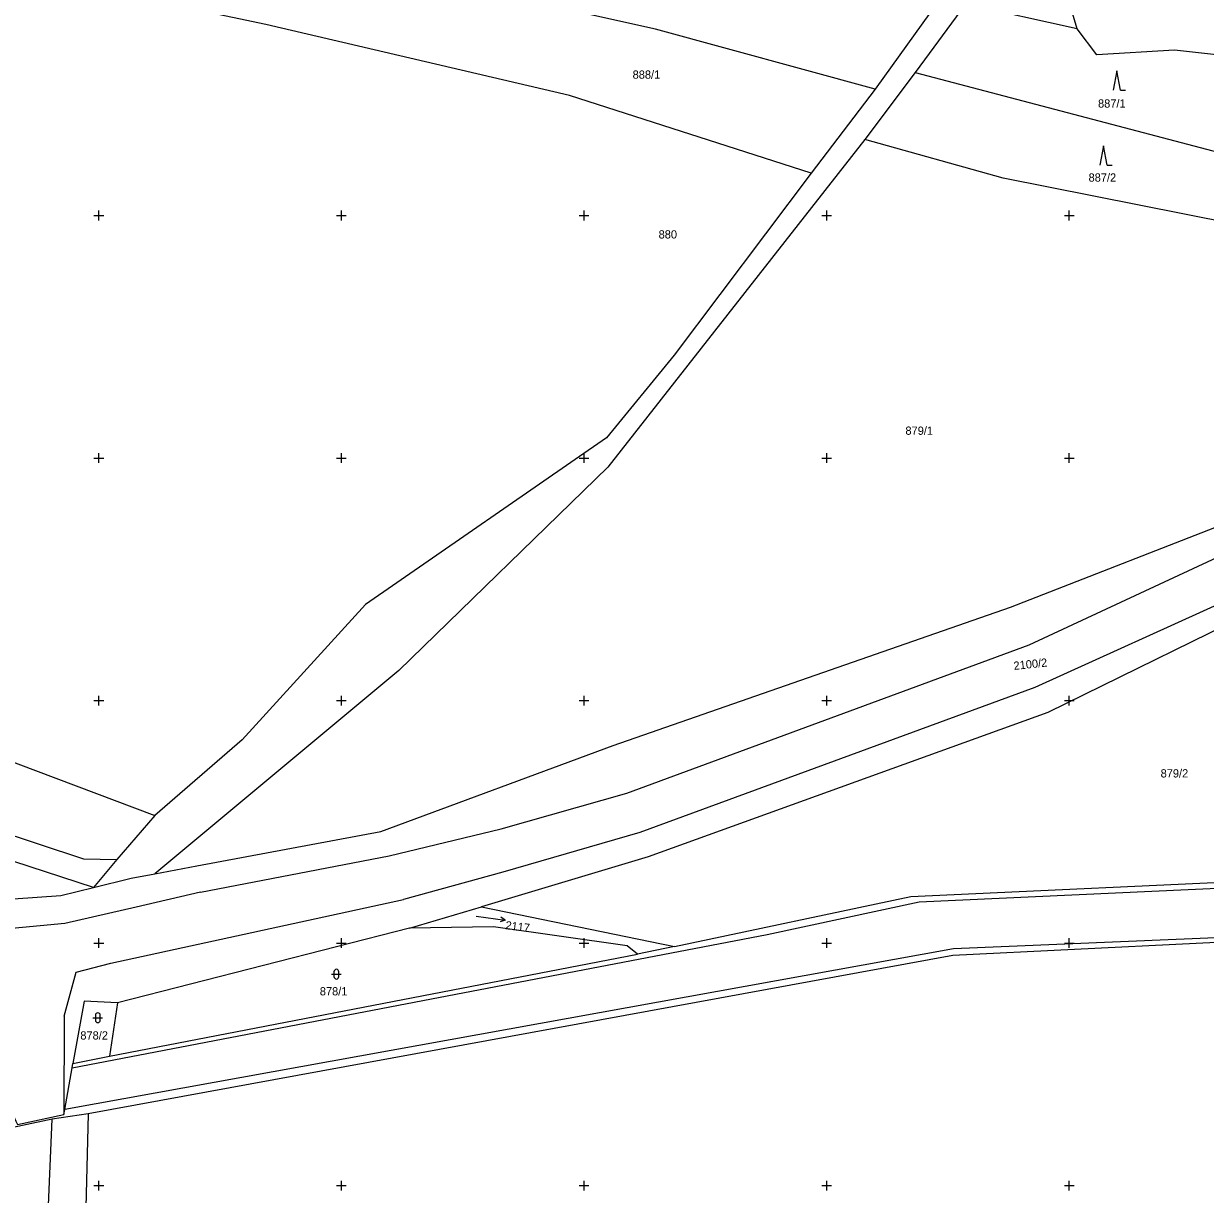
# Model space of a CAD drawing. Extents: x -776734 to -748832, y -1118122 to -976986.
# Drawn here: x -751615.5 to -751372, y -1114601.8 to -1114360.4 of the extents above; entities that cross this region are included whole.
import ezdxf

# ---------------------------------------------------------------- set-up
doc = ezdxf.new("R2010")
doc.units = 0
for name, color, linetype in [('KM_Hranice parcel', 7, 'Continuous'), ('KM_Parcelní čísla', 7, 'Continuous'), ('KM_Vnitřní kresba', 7, 'Continuous'), ('KM_Značky kultur', 7, 'Continuous'), ('Level 61 Křížky', 7, 'Continuous')]:
    doc.layers.add(name, color=color, linetype=linetype)

msp = doc.modelspace()

# ---------------------------------------------------------------- linework, layer by layer
at = {"layer": 'KM_Hranice parcel'}
for p, q in [((-751427.05, -1114355.89), (-751440, -1114373.97)), ((-751421.39, -1114356.4), (-751431.74, -1114370.53)), ((-751398.35, -1114361.51), (-751421.39, -1114356.4)), ((-751431.74, -1114370.53), (-751442.11, -1114384.32)), ((-751431.74, -1114370.53), (-751341.58, -1114394.27)), ((-751440, -1114373.97), (-751453.2, -1114391.28)), ((-751601.09, -1114538.53), (-751689.64, -1114509.75)), ((-751621.83, -1114511.12), (-751588.44, -1114523.72)), ((-751588.44, -1114523.72), (-751596.28, -1114532.8)), ((-751596.28, -1114532.8), (-751601.09, -1114538.53)), ((-751535.95, -1114546.94), (-751521.15, -1114542.51)), ((-751521.15, -1114542.51), (-751481.36, -1114550.68)), ((-751535.95, -1114546.94), (-751596.18, -1114562.31)), ((-751518.68, -1114546.66), (-751535.95, -1114546.94)), ((-751597.79, -1114573.33), (-751488.98, -1114552.3)), ((-751481.36, -1114550.68), (-751488.98, -1114552.3)), ((-751603.05, -1114561.97), (-751605.33, -1114574.82)), ((-751596.18, -1114562.31), (-751603.05, -1114561.97)), ((-751596.18, -1114562.31), (-751597.79, -1114573.33)), ((-751605.33, -1114574.82), (-751597.79, -1114573.33)), ((-751609.62, -1114586.32), (-751642.03, -1114593.16)), ((-751610.82, -1114613.8), (-751609.62, -1114586.32)), ((-751602.21, -1114585.19), (-751609.62, -1114586.32)), ((-751602.21, -1114585.19), (-751603.5, -1114635.12))]:
    msp.add_line(p, q, dxfattribs=at)
for points in [[(-751440, -1114373.97), (-751485.27, -1114361.58), (-751742.99, -1114304.3)], [(-751453.2, -1114391.28), (-751503.01, -1114375.24), (-751565.59, -1114360.64), (-751686.33, -1114335.17), (-751745.07, -1114320.79)], [(-751398.35, -1114361.51), (-751403.83, -1114343.32), (-751398.45, -1114331.48)], [(-751341.58, -1114394.27), (-751342.07, -1114392.17), (-751351.85, -1114388.94), (-751349.21, -1114369.18), (-751378.31, -1114365.92), (-751394.34, -1114366.89), (-751398.35, -1114361.51)], [(-751442.11, -1114384.32), (-751495.07, -1114451.91), (-751538.14, -1114493.82), (-751588.46, -1114535.7)], [(-751338.56, -1114407.2), (-751413.61, -1114392.32), (-751442.11, -1114384.32)], [(-751453.2, -1114391.28), (-751481.44, -1114428.78), (-751495.4, -1114445.83), (-751545.06, -1114480.22), (-751570.45, -1114508.09), (-751588.44, -1114523.72)], [(-751588.46, -1114535.7), (-751579.83, -1114534.11), (-751541.9, -1114526.98), (-751493.98, -1114509.24), (-751412.14, -1114480.78), (-751314.14, -1114442.52)], [(-751308.12, -1114455.16), (-751404.41, -1114502.47), (-751486.76, -1114532.2), (-751521.15, -1114542.51)], [(-751481.36, -1114550.68), (-751432.68, -1114540.38), (-751355.26, -1114536.81), (-751275.2, -1114497.24)], [(-751687.49, -1114504.72), (-751603.17, -1114532.66), (-751596.28, -1114532.8)], [(-751268.49, -1114506.51), (-751348.8, -1114548.84), (-751424.02, -1114552.57), (-751602.21, -1114585.19)], [(-751601.09, -1114538.53), (-751593.31, -1114536.6), (-751588.46, -1114535.7)], [(-751665.45, -1114544.23), (-751607.84, -1114540.2), (-751601.09, -1114538.53)], [(-751488.98, -1114552.3), (-751491.11, -1114550.56), (-751518.68, -1114546.66)], [(-751621.11, -1114577.93), (-751620.76, -1114578.69), (-751617.1, -1114586.71), (-751616.79, -1114587.38), (-751607.19, -1114585.33), (-751607, -1114584.28), (-751605.49, -1114575.75), (-751605.33, -1114574.82)]]:
    msp.add_lwpolyline(points, dxfattribs=at)
at = {"layer": 'KM_Vnitřní kresba'}
for p, q in [((-751408.27, -1114488.53), (-751313.34, -1114444.27)), ((-751309.29, -1114452.86), (-751407.07, -1114497.33)), ((-751491.18, -1114519.1), (-751408.27, -1114488.53)), ((-751407.07, -1114497.33), (-751488.49, -1114527.19)), ((-751517.11, -1114526.48), (-751491.18, -1114519.1)), ((-751540.16, -1114532.01), (-751517.11, -1114526.48)), ((-751488.49, -1114527.19), (-751516.72, -1114535.38)), ((-751579.06, -1114539.53), (-751540.16, -1114532.01)), ((-751516.72, -1114535.38), (-751537.2, -1114541.02)), ((-751579.06, -1114539.53), (-751592.28, -1114542.58)), ((-751430.97, -1114541.48), (-751354.45, -1114537.96)), ((-751592.28, -1114542.58), (-751606.98, -1114545.97)), ((-751597.53, -1114554.13), (-751537.2, -1114541.02)), ((-751462.24, -1114548.25), (-751430.97, -1114541.48)), ((-751606.98, -1114545.97), (-751685.68, -1114553.29)), ((-751531.41, -1114561.5), (-751462.24, -1114548.25)), ((-751350.22, -1114548.07), (-751423.89, -1114551.2)), ((-751423.89, -1114551.2), (-751607, -1114584.28)), ((-751604.68, -1114556.02), (-751597.53, -1114554.13)), ((-751607.11, -1114565.08), (-751604.68, -1114556.02)), ((-751605.49, -1114575.75), (-751531.41, -1114561.5)), ((-751607.11, -1114565.08), (-751607.19, -1114585.33))]:
    msp.add_line(p, q, dxfattribs=at)
at = {"layer": 'KM_Značky kultur'}
for p, q in [((-751390.19, -1114370.17), (-751390.94, -1114374.17)), ((-751389.44, -1114374.17), (-751390.19, -1114370.17)), ((-751389.44, -1114374.17), (-751388.444, -1114374.17)), ((-751392.93, -1114385.63), (-751393.68, -1114389.63)), ((-751392.18, -1114389.63), (-751392.93, -1114385.63)), ((-751392.18, -1114389.63), (-751391.184, -1114389.63)), ((-751522.205, -1114544.423), (-751516.263, -1114545.258)), ((-751516.263, -1114545.258), (-751517.161, -1114544.626)), ((-751516.263, -1114545.258), (-751517.301, -1114545.619)), ((-751552.041, -1114556.411), (-751550.039, -1114556.411)), ((-751551.541, -1114555.911), (-751551.541, -1114556.912)), ((-751550.539, -1114556.912), (-751550.539, -1114555.911)), ((-751601.211, -1114565.381), (-751599.209, -1114565.381)), ((-751600.711, -1114564.881), (-751600.711, -1114565.882)), ((-751599.709, -1114565.882), (-751599.709, -1114564.881))]:
    msp.add_line(p, q, dxfattribs=at)
for centre, start, end in [((-751551.04, -1114555.9109), 0, 180), ((-751551.04, -1114556.9109), 180, 359.987886), ((-751600.21, -1114564.8809), 0, 180), ((-751600.21, -1114565.8809), 180, 359.987886)]:
    msp.add_arc(centre, 0.5, start, end, dxfattribs=at)
at = {"layer": 'Level 61 Křížky'}
for p, q in [((-751600, -1114400), (-751600, -1114399)), ((-751550, -1114400), (-751550, -1114399)), ((-751500, -1114400), (-751500, -1114399)), ((-751450, -1114400), (-751450, -1114399)), ((-751400, -1114400), (-751400, -1114399)), ((-751601, -1114400), (-751599, -1114400)), ((-751600, -1114401), (-751600, -1114400)), ((-751551, -1114400), (-751549, -1114400)), ((-751550, -1114401), (-751550, -1114400)), ((-751501, -1114400), (-751499, -1114400)), ((-751500, -1114401), (-751500, -1114400)), ((-751451, -1114400), (-751449, -1114400)), ((-751450, -1114401), (-751450, -1114400)), ((-751401, -1114400), (-751399, -1114400)), ((-751400, -1114401), (-751400, -1114400)), ((-751601, -1114450), (-751599, -1114450)), ((-751600, -1114450), (-751600, -1114449)), ((-751600, -1114451), (-751600, -1114450)), ((-751551, -1114450), (-751549, -1114450)), ((-751550, -1114450), (-751550, -1114449)), ((-751550, -1114451), (-751550, -1114450)), ((-751501, -1114450), (-751499, -1114450)), ((-751500, -1114450), (-751500, -1114449)), ((-751500, -1114451), (-751500, -1114450)), ((-751451, -1114450), (-751449, -1114450)), ((-751450, -1114450), (-751450, -1114449)), ((-751450, -1114451), (-751450, -1114450)), ((-751401, -1114450), (-751399, -1114450)), ((-751400, -1114450), (-751400, -1114449)), ((-751400, -1114451), (-751400, -1114450)), ((-751601, -1114500), (-751599, -1114500)), ((-751600, -1114500), (-751600, -1114499)), ((-751600, -1114501), (-751600, -1114500)), ((-751551, -1114500), (-751549, -1114500)), ((-751550, -1114500), (-751550, -1114499)), ((-751550, -1114501), (-751550, -1114500)), ((-751501, -1114500), (-751499, -1114500)), ((-751500, -1114500), (-751500, -1114499)), ((-751500, -1114501), (-751500, -1114500)), ((-751451, -1114500), (-751449, -1114500)), ((-751450, -1114500), (-751450, -1114499)), ((-751450, -1114501), (-751450, -1114500)), ((-751401, -1114500), (-751399, -1114500)), ((-751400, -1114500), (-751400, -1114499)), ((-751400, -1114501), (-751400, -1114500)), ((-751601, -1114550), (-751599, -1114550)), ((-751600, -1114550), (-751600, -1114549)), ((-751600, -1114551), (-751600, -1114550)), ((-751551, -1114550), (-751549, -1114550)), ((-751550, -1114550), (-751550, -1114549)), ((-751550, -1114551), (-751550, -1114550)), ((-751501, -1114550), (-751499, -1114550)), ((-751500, -1114550), (-751500, -1114549)), ((-751500, -1114551), (-751500, -1114550)), ((-751451, -1114550), (-751449, -1114550)), ((-751450, -1114550), (-751450, -1114549)), ((-751450, -1114551), (-751450, -1114550)), ((-751401, -1114550), (-751399, -1114550)), ((-751400, -1114550), (-751400, -1114549)), ((-751400, -1114551), (-751400, -1114550)), ((-751601, -1114600), (-751599, -1114600)), ((-751600, -1114600), (-751600, -1114599)), ((-751600, -1114601), (-751600, -1114600)), ((-751551, -1114600), (-751549, -1114600)), ((-751550, -1114600), (-751550, -1114599)), ((-751550, -1114601), (-751550, -1114600)), ((-751501, -1114600), (-751499, -1114600)), ((-751500, -1114600), (-751500, -1114599)), ((-751500, -1114601), (-751500, -1114600)), ((-751451, -1114600), (-751449, -1114600)), ((-751450, -1114600), (-751450, -1114599)), ((-751450, -1114601), (-751450, -1114600)), ((-751401, -1114600), (-751399, -1114600)), ((-751400, -1114600), (-751400, -1114599)), ((-751400, -1114601), (-751400, -1114600))]:
    msp.add_line(p, q, dxfattribs=at)

# ---------------------------------------------------------------- texts
at = {"layer": 'KM_Parcelní čísla'}
for s, p in [('888/1', (-751489.9919, -1114371.805)), ('887/1', (-751394.078, -1114377.76)), ('887/2', (-751396.028, -1114393.02)), ('880', (-751484.6347, -1114404.7464)), ('879/1', (-751433.768, -1114445.21)), ('879/2', (-751381.178, -1114515.86)), ('878/1', (-751554.458, -1114560.79)), ('878/2', (-751603.81, -1114569.89))]:
    msp.add_text(s, height=1.7, dxfattribs=at).set_placement(p)
for s, rotation, p in [('2100/2', 6, (-751411.3904, -1114493.7007)), ('2117', 353, (-751516.285, -1114547.131))]:
    msp.add_text(s, height=1.7, rotation=rotation, dxfattribs=at).set_placement(p)

doc.saveas('drawing.dxf')
